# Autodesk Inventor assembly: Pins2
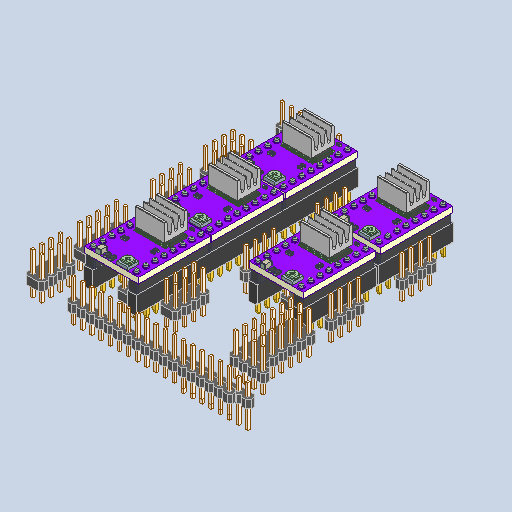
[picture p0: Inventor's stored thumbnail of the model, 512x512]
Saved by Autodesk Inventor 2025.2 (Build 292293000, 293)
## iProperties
Created: 2025-04
Part Number: Pins2
Description: PART--DESC
Document SubType Name: Assembly
Designer: BennF
Author: BennF
Revision Number: NONE
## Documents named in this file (24)
- C:\Users\BennF\Nextcloud\Benutzer\CNC JarBeRi\existing parts\Electronics\RepRap A4988 Shied (USE WITHOUT ARDUINO)\reprap-a4988-1.snapshot.1\RepRap\RepRap\Pins2.iam
- C:\Users\BennF\Nextcloud\Benutzer\CNC JarBeRi\existing parts\Electronics\RepRap A4988 Shied (USE WITHOUT ARDUINO)\reprap-a4988-1.snapshot.1\RepRap\RepRap\6x3M.iam
- C:\Users\BennF\Nextcloud\Benutzer\CNC JarBeRi\existing parts\Electronics\RepRap A4988 Shied (USE WITHOUT ARDUINO)\reprap-a4988-1.snapshot.1\RepRap\RepRap\8Fset.iam
- C:\Users\BennF\Nextcloud\Benutzer\CNC JarBeRi\existing parts\Electronics\RepRap A4988 Shied (USE WITHOUT ARDUINO)\reprap-a4988-1.snapshot.1\RepRap\RepRap\8Fset_1.iam
- C:\Users\BennF\Nextcloud\Benutzer\CNC JarBeRi\existing parts\Electronics\RepRap A4988 Shied (USE WITHOUT ARDUINO)\reprap-a4988-1.snapshot.1\RepRap\RepRap\8M.iam
- C:\Users\BennF\Nextcloud\Benutzer\CNC JarBeRi\existing parts\Electronics\RepRap A4988 Shied (USE WITHOUT ARDUINO)\reprap-a4988-1.snapshot.1\RepRap\RepRap\4M.iam
- C:\Users\BennF\Nextcloud\Benutzer\CNC JarBeRi\existing parts\Electronics\RepRap A4988 Shied (USE WITHOUT ARDUINO)\reprap-a4988-1.snapshot.1\RepRap\RepRap\4M_1.iam
- C:\Users\BennF\Nextcloud\Benutzer\CNC JarBeRi\existing parts\Electronics\RepRap A4988 Shied (USE WITHOUT ARDUINO)\reprap-a4988-1.snapshot.1\RepRap\RepRap\24F-set.iam
- C:\Users\BennF\Nextcloud\Benutzer\CNC JarBeRi\existing parts\Electronics\RepRap A4988 Shied (USE WITHOUT ARDUINO)\reprap-a4988-1.snapshot.1\RepRap\RepRap\4x3M.iam
- C:\Users\BennF\Nextcloud\Benutzer\CNC JarBeRi\existing parts\Electronics\RepRap A4988 Shied (USE WITHOUT ARDUINO)\reprap-a4988-1.snapshot.1\RepRap\RepRap\4x2M.iam
- C:\Users\BennF\Nextcloud\Benutzer\CNC JarBeRi\existing parts\Electronics\RepRap A4988 Shied (USE WITHOUT ARDUINO)\reprap-a4988-1.snapshot.1\RepRap\RepRap\4x2M_1.iam
- C:\Users\BennF\Nextcloud\Benutzer\CNC JarBeRi\existing parts\Electronics\RepRap A4988 Shied (USE WITHOUT ARDUINO)\reprap-a4988-1.snapshot.1\RepRap\RepRap\5x2M.iam
- C:\Users\BennF\Nextcloud\Benutzer\CNC JarBeRi\existing parts\Electronics\RepRap A4988 Shied (USE WITHOUT ARDUINO)\reprap-a4988-1.snapshot.1\RepRap\RepRap\4M_2.iam
- C:\Users\BennF\Nextcloud\Benutzer\CNC JarBeRi\existing parts\Electronics\RepRap A4988 Shied (USE WITHOUT ARDUINO)\reprap-a4988-1.snapshot.1\RepRap\RepRap\4M_3.iam
- C:\Users\BennF\Nextcloud\Benutzer\CNC JarBeRi\existing parts\Electronics\RepRap A4988 Shied (USE WITHOUT ARDUINO)\reprap-a4988-1.snapshot.1\RepRap\RepRap\3x2.iam
- C:\Users\BennF\Nextcloud\Benutzer\CNC JarBeRi\existing parts\Electronics\RepRap A4988 Shied (USE WITHOUT ARDUINO)\reprap-a4988-1.snapshot.1\RepRap\RepRap\4x2M_2.iam
- C:\Users\BennF\Nextcloud\Benutzer\CNC JarBeRi\existing parts\Electronics\RepRap A4988 Shied (USE WITHOUT ARDUINO)\reprap-a4988-1.snapshot.1\RepRap\RepRap\3x2_1.iam
- C:\Users\BennF\Nextcloud\Benutzer\CNC JarBeRi\existing parts\Electronics\RepRap A4988 Shied (USE WITHOUT ARDUINO)\reprap-a4988-1.snapshot.1\RepRap\RepRap\3x2_2.iam
- C:\Users\BennF\Nextcloud\Benutzer\CNC JarBeRi\existing parts\Electronics\RepRap A4988 Shied (USE WITHOUT ARDUINO)\reprap-a4988-1.snapshot.1\RepRap\RepRap\3x2_3.iam
- C:\Users\BennF\Nextcloud\Benutzer\CNC JarBeRi\existing parts\Electronics\RepRap A4988 Shied (USE WITHOUT ARDUINO)\reprap-a4988-1.snapshot.1\RepRap\RepRap\3x2_4.iam
- C:\Users\BennF\Nextcloud\Benutzer\CNC JarBeRi\existing parts\Electronics\RepRap A4988 Shied (USE WITHOUT ARDUINO)\reprap-a4988-1.snapshot.1\RepRap\RepRap\18M.iam
- C:\Users\BennF\Nextcloud\Benutzer\CNC JarBeRi\existing parts\Electronics\RepRap A4988 Shied (USE WITHOUT ARDUINO)\reprap-a4988-1.snapshot.1\RepRap\RepRap\2M.iam
- C:\Users\BennF\Nextcloud\Benutzer\CNC JarBeRi\existing parts\Electronics\RepRap A4988 Shied (USE WITHOUT ARDUINO)\reprap-a4988-1.snapshot.1\RepRap\RepRap\3M.iam
- C:\Users\BennF\Nextcloud\Benutzer\CNC JarBeRi\existing parts\Electronics\RepRap A4988 Shied (USE WITHOUT ARDUINO)\reprap-a4988-1.snapshot.1\RepRap\RepRap\4M_4.iam
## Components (23 placed, 12 different names)
1. 6x3M [sub-assembly]
2. 8Fset [sub-assembly]
3. 8Fset:1 [sub-assembly]
4. 8M [sub-assembly]
5. 4M [sub-assembly]
6. 4M:1 [sub-assembly]
7. 24F-set [sub-assembly]
8. 4x3M [sub-assembly]
9. 4x2M [sub-assembly]
10. 4x2M:1 [sub-assembly]
11. 5x2M [sub-assembly]
12. 4M:2 [sub-assembly]
13. 4M:3 [sub-assembly]
14. 3x2 [sub-assembly]
15. 4x2M:2 [sub-assembly]
16. 3x2:1 [sub-assembly]
17. 3x2:2 [sub-assembly]
18. 3x2:3 [sub-assembly]
19. 3x2:4 [sub-assembly]
20. 18M [sub-assembly]
21. 2M [sub-assembly]
22. 3M [sub-assembly]
23. 4M:4 [sub-assembly]
